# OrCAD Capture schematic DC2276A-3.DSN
size Custom; title: -36V, 1.5A NEGATIVE LINEAR REGULATOR; rev: 3; note: DEMO CIRCUIT 2276A
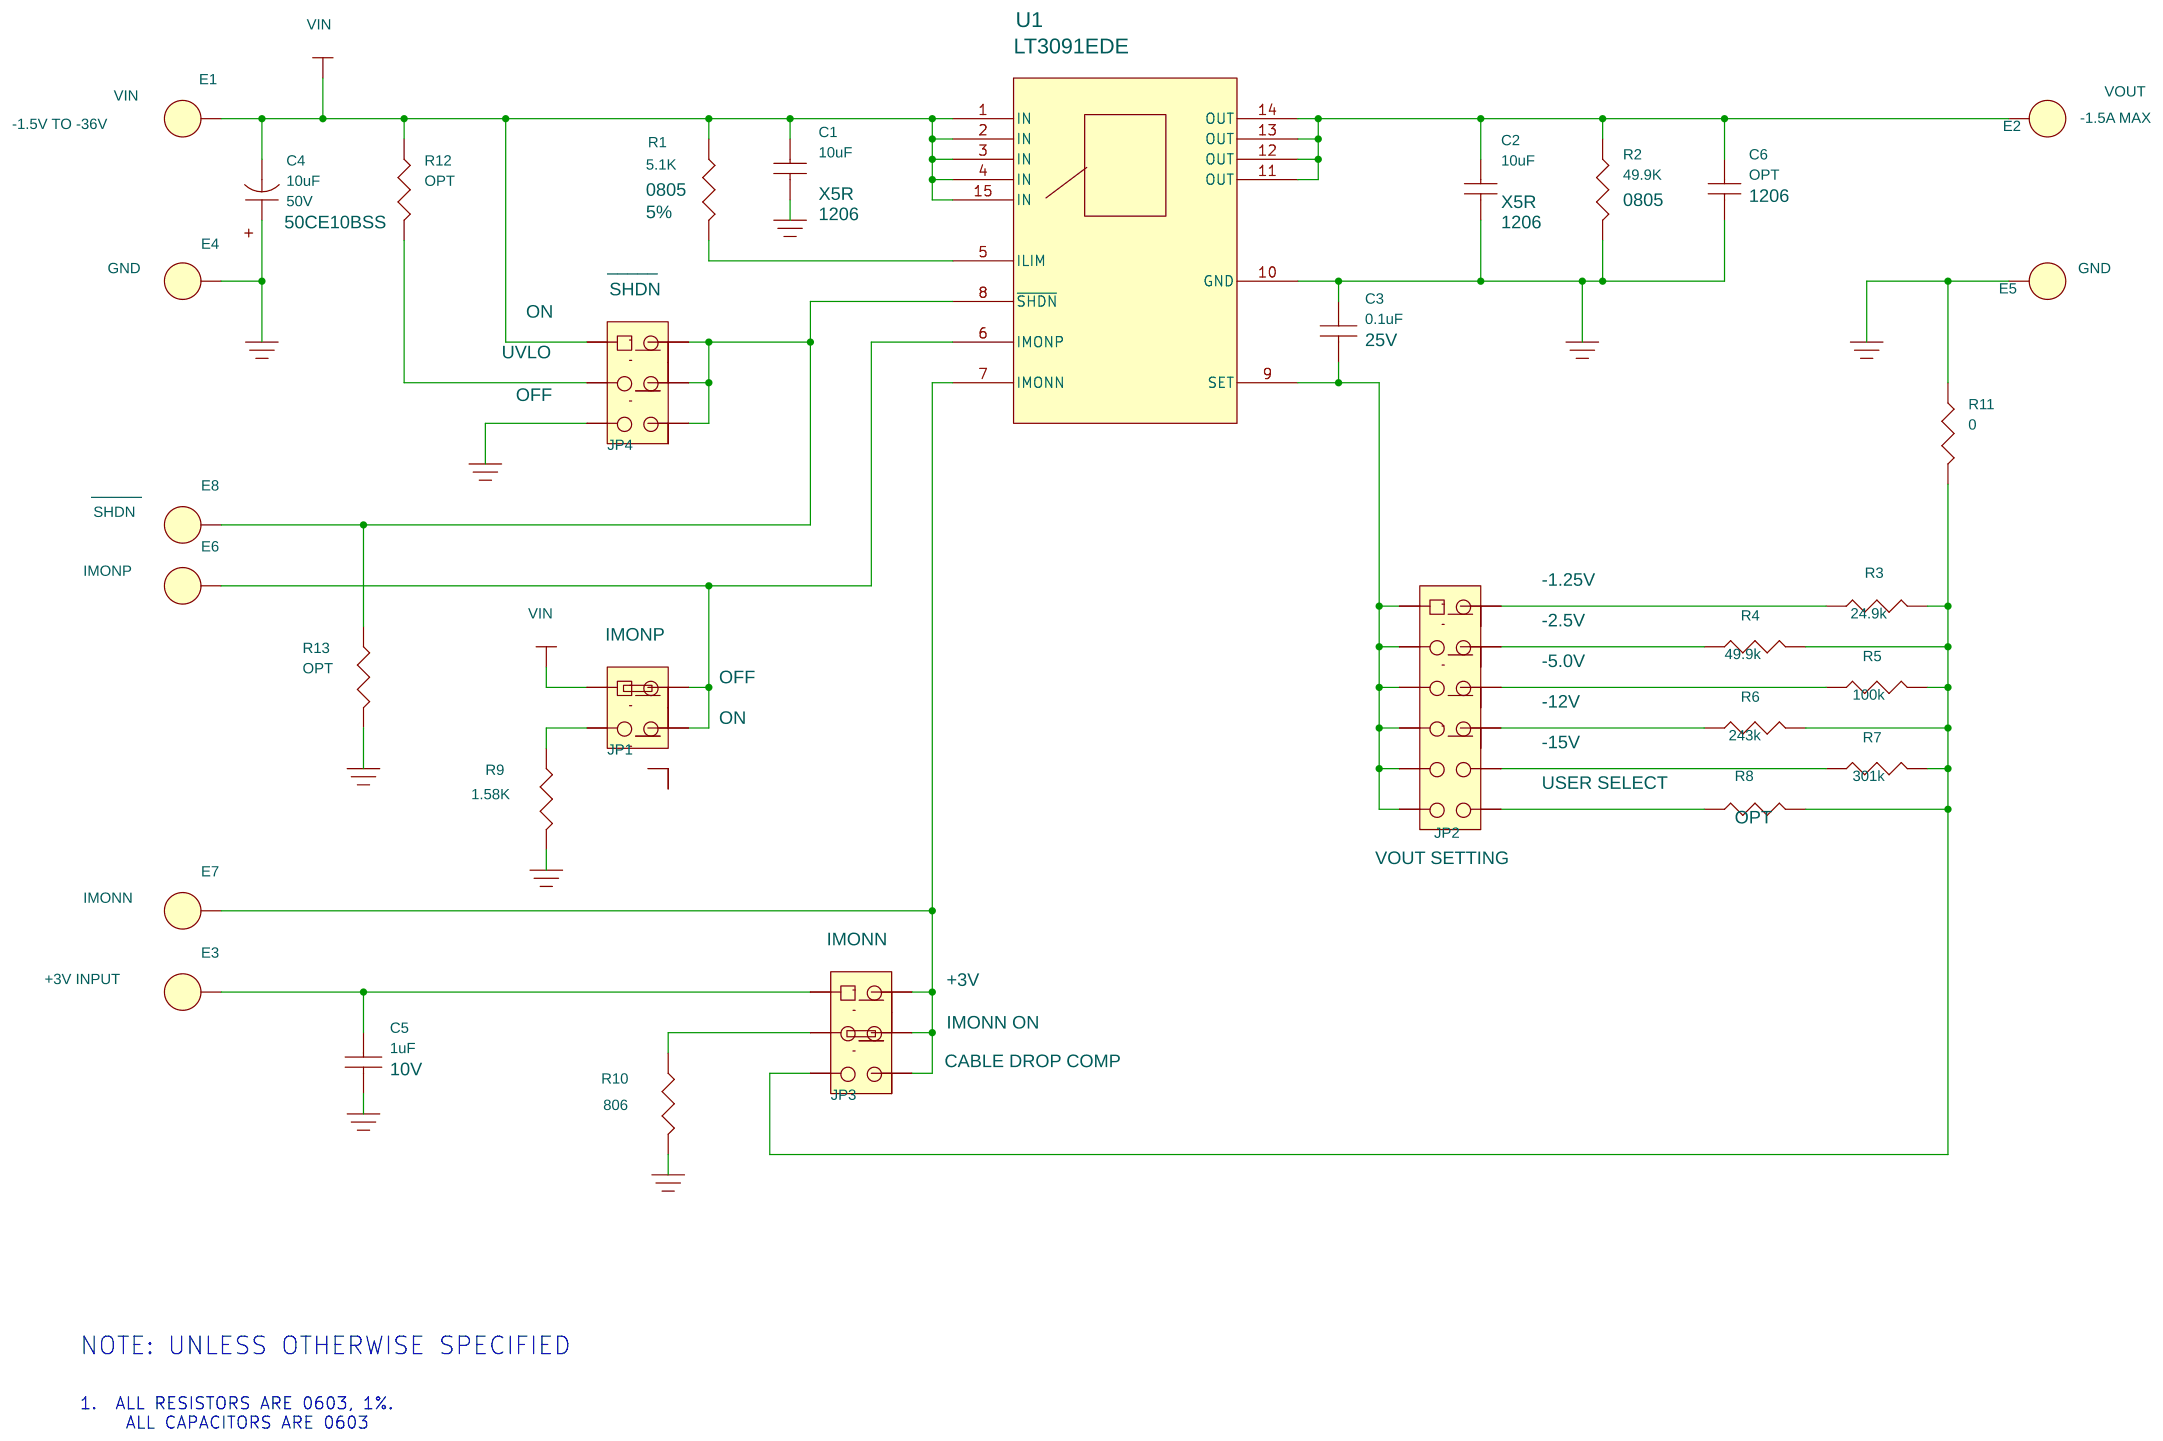
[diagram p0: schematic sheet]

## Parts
C1  10uF  [1206]
C2  10uF  [1206]
C3  0.1uF  [0603]
C4  10uF  [CAP-CE-5x5.4]
C5  1uF  [0603]
C6  OPT  [1206]
E1  Testpoint  [PAD150-094]
E2  Testpoint  [PAD150-094]
E3  Testpoint  [PAD150-094]
E4  Testpoint  [PAD150-094]
E5  Testpoint  [PAD150-094]
E6  Testpoint  [PAD150-094]
E7  Testpoint  [PAD150-094]
E8  Testpoint  [PAD150-094]
JP1  JP2X2/079  [JP2X2/079]
JP2  JP6X2/079  [JP6X2/079]
JP3  JP2X3/079  [JP2X3/079]
JP4  JP2X3/079  [JP2X3/079]
R1  5.1K  [0805]
R2  49.9K  [0805]
R3  24.9k  [0603]
R4  49.9k  [0603]
R5  100k  [0603]
R6  243k  [0603]
R7  301k  [0603]
R8  OPT  [0603]
R9  1.58K  [0603]
R10  806  [0603]
R11  0  [0603]
R12  OPT  [0603]
R13  OPT  [0603]
U1  Regulator  [DFN-14(4X3)]
XJP1  2mm Ctrs.
XJP2  2mm Ctrs.
XJP3  2mm Ctrs.
XJP4  2mm Ctrs.

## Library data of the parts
C1 = GRM31CR61H225KA88K_2: 3rd Part Field: X5R
C2 = GRM31CR61H225KA88K: 3rd Part Field: X5R
C3 = 0402YC103MAT2A: 1st Part Field: 25V
C4 = CAP-CE-6.3X5_0.4: 1ST PART FIELD: 50V; 4TH PART FIELD: SUNCON; 5TH PART FIELD: 50CE10BSS
C5 = 0402YC103MAT2A: 1st Part Field: 10V
C6 = GRM31CR61H225KA88K_1
E1 = MillMax-2501: 10th Part Field: -1.5V TO -36V; 9th Part Field: VIN
E2 = MillMax-2501: 10th Part Field: -1.5A MAX; 11th Part Field: MAX; 9th Part Field: VOUT
E3 = MillMax-2501: 10th Part Field: +3V INPUT; 11TH PART FIELD: _____; 9th Part Field: VIN
E4 E5 = MillMax-2501: 10th Part Field: GND; 9th Part Field: VIN
E6 = MillMax-2501: 10th Part Field: IMONP; 11TH PART FIELD: _____; 9th Part Field: VIN
E7 = MillMax-2501: 10th Part Field: IMONN; 11TH PART FIELD: _____; 9th Part Field: VIN
E8 = MillMax-2501: 10th Part Field: SHDN; 11TH PART FIELD: _____; 9th Part Field: VIN
JP1 = JP2X2_079: 10TH PART FIELD: IMONP; 8TH PART FIELD: OFF; 9TH PART FIELD: ON
JP2 = JP6X2_079: 10TH PART FIELD: -5.0V; 11TH PART FIELD: -12V; 12TH PART FIELD: -15V; 13TH PART FIELD: USER SELECT; 14TH PART FIELD: VOUT SETTING; 4TH PART FIELD: SAMTEC,; 8TH PART FIELD: -1.25V; 9TH PART FIELD: -2.5V
JP3 = JP2X3_079: 10TH PART FIELD: CABLE DROP COMP; 11TH PART FIELD: IMONN; 8TH PART FIELD: +3V; 9TH PART FIELD: IMONN ON
JP4 = JP2X3_079: 4TH PART FIELD: SHDN; 5TH PART FIELD: _____; 6TH PART FIELD: ON; 8TH PART FIELD: OFF; 9TH PART FIELD: UVLO
R1 = CRCW0402124KFKED: 2nd Part Field: 5%
R2 R9-R13 = CRCW0402124KFKED
R3 = CRCW0402249KFKED
R4 = CRCW0402287KFKED
R5 = CRCW0402392KFKED
R6 = CRCW0402562KFKED
R7 = CRCW0402909KFKED
R8 = RES0402
U1 = LT3060EDC_11: 5th Part Field: LT3091EDE
XJP1-XJP4 = Samtec_2SN-BK-G_10

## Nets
GND: C1.2 C2.2 C3.1 C4.1 C5.2 C6.2 E4.1 E5.1 JP4.5 R2.2 R9.2 R10.2 R11.1 R13.2 U1.10(GND)
VIN: C1.1 C4.2 E1.1 JP1.1 JP4.1 R1.1 R12.1 U1.1(IN) U1.2(IN) U1.3(IN) U1.4(IN) U1.15(IN)
N16893850: JP4.3 R12.2
N16938106: C2.1 C6.1 E2.1 R2.1 U1.11(OUT) U1.12(OUT) U1.13(OUT) U1.14(OUT)
N16973634: E8.1 JP4.2 JP4.4 JP4.6 R13.1 U1.8(~{SHDN})
N17010383: R1.2 U1.5(ILIM)
N17036525: E6.1 JP1.2 JP1.4 U1.6(IMONP)
N17050558: JP1.3 R9.1
N17053968: E7.1 JP3.2 JP3.4 JP3.6 U1.7(IMONN)
N17056697: C5.1 E3.1 JP3.1
N17061500: JP3.3 R10.1
N17076777: C3.2 JP2.1 JP2.3 JP2.5 JP2.7 JP2.9 JP2.11 U1.9(SET)
N17083085: JP2.2 R3.1
N17084674: JP2.4 R4.1
N17087102: JP3.5 R3.2 R4.2 R5.2 R6.2 R7.2 R8.2 R11.2
N17087563: JP2.6 R5.1
N17087877: JP2.8 R6.1
N17088199: JP2.10 R7.1
N17089634: JP2.12 R8.1

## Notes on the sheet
- NOTE: UNLESS OTHERWISE SPECIFIED
- 1.  ALL RESISTORS ARE 0603, 1%.
       ALL CAPACITORS ARE 0603
